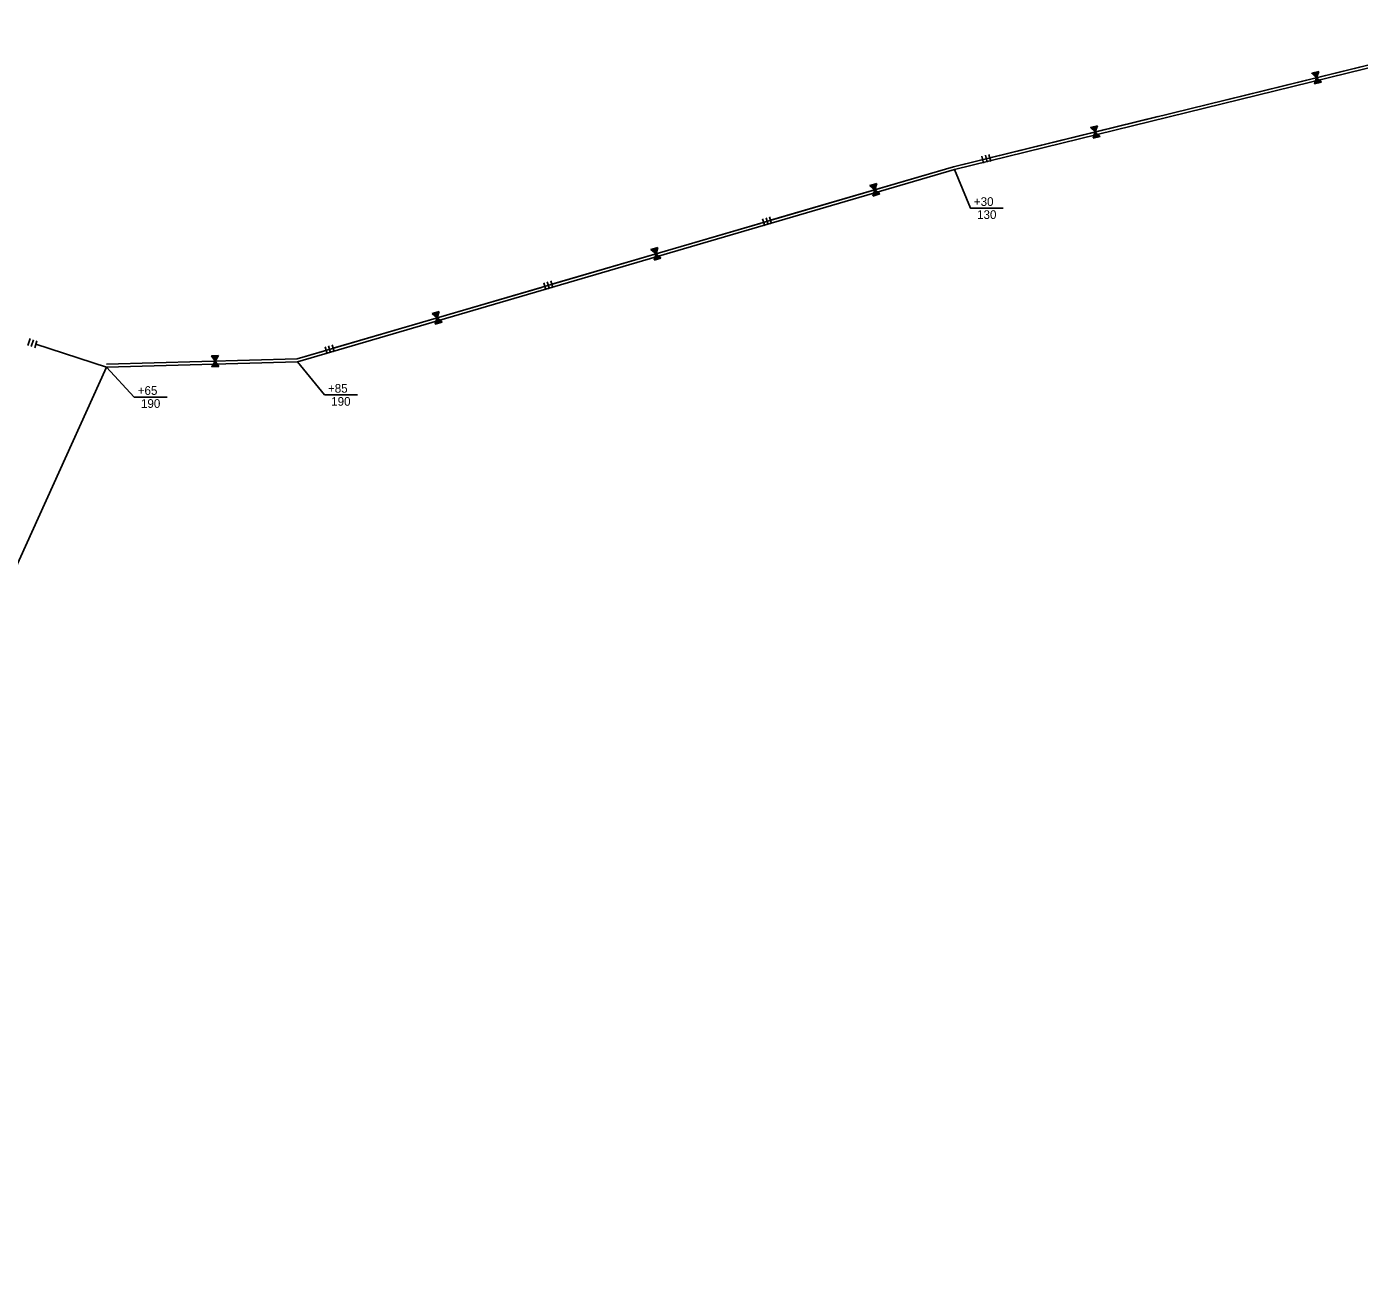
# Model space of a CAD drawing. Extents: x 979729 to 993523, y 1834148 to 1845433.
# Drawn here: x 984124 to 985045, y 1836905 to 1837770 of the extents above; entities that cross this region are included whole.
import ezdxf

# ---------------------------------------------------------------- set-up
doc = ezdxf.new("R2010")
doc.units = 0
for name, color, linetype in [('42', 7, 'Continuous'), ('51', 7, 'Continuous'), ('R_Draft', 7, 'Continuous')]:
    doc.layers.add(name, color=color, linetype=linetype)

msp = doc.modelspace()

# ---------------------------------------------------------------- linework, layer by layer
at = {"layer": '42'}
for p, q in [((984764.91, 1837673.05), (985159.48, 1837769.83)), ((985012.42, 1837737.62), (985015.74, 1837734.58)), ((985012.49, 1837737.58), (985012.51, 1837737.64)), ((985012.69, 1837737.42), (985012.8, 1837737.72)), ((985012.89, 1837737.22), (985013.09, 1837737.79)), ((985013.09, 1837737.05), (985013.38, 1837737.86)), ((985013.28, 1837736.85), (985013.68, 1837737.93)), ((985013.48, 1837736.65), (985013.97, 1837738)), ((985013.68, 1837736.49), (985014.26, 1837738.07)), ((985013.91, 1837736.38), (985014.49, 1837737.99)), ((985014.09, 1837736.15), (985014.84, 1837738.22)), ((985014.2, 1837730.34), (985015.74, 1837734.58)), ((985014.3, 1837735.98), (985015.14, 1837738.29)), ((985014.48, 1837735.75), (985015.43, 1837738.36)), ((985014.7, 1837735.62), (985015.72, 1837738.43)), ((985014.88, 1837735.39), (985016.01, 1837738.5)), ((985015.01, 1837732.42), (985016.63, 1837730.93)), ((985015.09, 1837735.23), (985016.3, 1837738.58)), ((985015.11, 1837732.66), (985016.92, 1837731)), ((985015.17, 1837732.95), (985017.21, 1837731.08)), ((985015.28, 1837735.02), (985016.59, 1837738.65)), ((985015.3, 1837733.17), (985017.51, 1837731.15)), ((985015.36, 1837733.46), (985017.8, 1837731.22)), ((985015.46, 1837733.7), (985018.09, 1837731.29)), ((985015.5, 1837734.89), (985016.89, 1837738.72)), ((985015.54, 1837733.97), (985018.38, 1837731.36)), ((985015.67, 1837734.19), (985018.67, 1837731.43)), ((985015.68, 1837734.66), (985017.18, 1837738.79)), ((985015.72, 1837734.48), (985018.96, 1837731.51)), ((985015.74, 1837734.58), (985017.27, 1837738.81)), ((985015.74, 1837734.58), (985019.06, 1837731.53)), ((985014.25, 1837730.41), (985014.29, 1837730.36)), ((985014.35, 1837730.65), (985014.59, 1837730.43)), ((985014.43, 1837730.91), (985014.88, 1837730.5)), ((985014.54, 1837731.15), (985015.17, 1837730.58)), ((985014.62, 1837731.42), (985015.46, 1837730.65)), ((985014.69, 1837731.69), (985015.75, 1837730.72)), ((985014.8, 1837731.93), (985016.05, 1837730.79)), ((985014.96, 1837732.13), (985016.21, 1837730.97)), ((984859.45, 1837700.1), (984862.77, 1837697.06)), ((984859.52, 1837700.07), (984859.54, 1837700.13)), ((984859.73, 1837699.9), (984859.83, 1837700.2)), ((984859.92, 1837699.7), (984860.13, 1837700.27)), ((984860.13, 1837699.54), (984860.42, 1837700.34)), ((984860.32, 1837699.33), (984860.71, 1837700.41)), ((984860.51, 1837699.13), (984861, 1837700.48)), ((984860.72, 1837698.97), (984861.29, 1837700.56)), ((984860.95, 1837698.87), (984861.53, 1837700.47)), ((984861.13, 1837698.63), (984861.88, 1837700.7)), ((984861.24, 1837692.82), (984862.77, 1837697.06)), ((984861.33, 1837698.46), (984862.17, 1837700.77)), ((984861.52, 1837698.24), (984862.46, 1837700.84)), ((984861.73, 1837698.1), (984862.75, 1837700.91)), ((984861.92, 1837697.87), (984863.04, 1837700.99)), ((984862.12, 1837697.71), (984863.34, 1837701.06)), ((984862.31, 1837697.5), (984863.63, 1837701.13)), ((984862.33, 1837695.65), (984864.54, 1837693.63)), ((984862.39, 1837695.94), (984864.83, 1837693.7)), ((984862.5, 1837696.18), (984865.12, 1837693.77)), ((984862.53, 1837697.37), (984863.92, 1837701.2)), ((984862.57, 1837696.45), (984865.41, 1837693.84)), ((984862.7, 1837696.67), (984865.71, 1837693.92)), ((984862.71, 1837697.14), (984864.21, 1837701.27)), ((984862.76, 1837696.96), (984866, 1837693.99)), ((984862.77, 1837697.06), (984864.31, 1837701.3)), ((984862.77, 1837697.06), (984866.09, 1837694.01)), ((984861.28, 1837692.89), (984861.33, 1837692.84)), ((984861.39, 1837693.13), (984861.62, 1837692.91)), ((984861.46, 1837693.4), (984861.91, 1837692.99)), ((984861.57, 1837693.64), (984862.2, 1837693.06)), ((984861.65, 1837693.91), (984862.5, 1837693.13)), ((984861.73, 1837694.17), (984862.79, 1837693.2)), ((984861.83, 1837694.41), (984863.08, 1837693.27)), ((984861.99, 1837694.61), (984863.25, 1837693.46)), ((984862.04, 1837694.9), (984863.66, 1837693.42)), ((984862.15, 1837695.15), (984863.96, 1837693.49)), ((984862.2, 1837695.43), (984864.25, 1837693.56)), ((984784.48, 1837680.43), (984785.67, 1837675.57)), ((984786.91, 1837681.03), (984788.1, 1837676.17)), ((984789.34, 1837681.62), (984790.53, 1837676.76)), ((984311.29, 1837540.32), (984764.91, 1837673.05)), ((984707, 1837660.02), (984710.46, 1837657.12)), ((984707.07, 1837659.98), (984707.09, 1837660.05)), ((984707.29, 1837659.83), (984707.38, 1837660.13)), ((984707.49, 1837659.63), (984707.67, 1837660.21)), ((984707.7, 1837659.48), (984707.96, 1837660.3)), ((984707.9, 1837659.29), (984708.25, 1837660.38)), ((984708.11, 1837659.1), (984708.54, 1837660.47)), ((984708.32, 1837658.94), (984708.82, 1837660.55)), ((984708.55, 1837658.85), (984709.06, 1837660.48)), ((984708.74, 1837658.62), (984709.4, 1837660.72)), ((984708.96, 1837658.46), (984709.69, 1837660.8)), ((984709.15, 1837658.24), (984709.98, 1837660.89)), ((984709.37, 1837658.12), (984710.27, 1837660.97)), ((984709.56, 1837657.9), (984710.55, 1837661.06)), ((984709.78, 1837657.74), (984710.84, 1837661.14)), ((984709.98, 1837657.55), (984711.13, 1837661.23)), ((984710.2, 1837657.42), (984711.42, 1837661.31)), ((984710.39, 1837657.2), (984711.71, 1837661.4)), ((984710.46, 1837657.12), (984711.8, 1837661.42)), ((984709.11, 1837652.82), (984710.46, 1837657.12)), ((984709.15, 1837652.89), (984709.2, 1837652.85)), ((984709.25, 1837653.13), (984709.49, 1837652.93)), ((984709.31, 1837653.41), (984709.78, 1837653.02)), ((984709.41, 1837653.65), (984710.07, 1837653.1)), ((984709.47, 1837653.92), (984710.35, 1837653.18)), ((984709.54, 1837654.19), (984710.64, 1837653.27)), ((984709.64, 1837654.44), (984710.93, 1837653.35)), ((984709.78, 1837654.64), (984711.09, 1837653.55)), ((984709.82, 1837654.94), (984711.51, 1837653.52)), ((984709.92, 1837655.18), (984711.8, 1837653.61)), ((984709.96, 1837655.47), (984712.08, 1837653.69)), ((984710.08, 1837655.7), (984712.37, 1837653.78)), ((984710.12, 1837655.99), (984712.66, 1837653.86)), ((984710.22, 1837656.23), (984712.95, 1837653.94)), ((984710.28, 1837656.51), (984713.24, 1837654.03)), ((984710.4, 1837656.73), (984713.53, 1837654.11)), ((984710.45, 1837657.02), (984713.81, 1837654.2)), ((984710.46, 1837657.12), (984713.91, 1837654.23)), ((984632.97, 1837637.05), (984634.38, 1837632.26)), ((984635.37, 1837637.76), (984636.78, 1837632.96)), ((984637.77, 1837638.46), (984639.18, 1837633.66)), ((984555.84, 1837615.79), (984559.3, 1837612.89)), ((984555.91, 1837615.75), (984555.93, 1837615.81)), ((984556.13, 1837615.6), (984556.22, 1837615.9)), ((984556.33, 1837615.4), (984556.51, 1837615.98)), ((984556.54, 1837615.25), (984556.8, 1837616.07)), ((984556.74, 1837615.06), (984557.09, 1837616.15)), ((984556.94, 1837614.86), (984557.37, 1837616.24)), ((984557.16, 1837614.71), (984557.66, 1837616.32)), ((984557.39, 1837614.61), (984557.9, 1837616.25)), ((984557.58, 1837614.39), (984558.24, 1837616.49)), ((984557.8, 1837614.23), (984558.53, 1837616.57)), ((984557.95, 1837608.59), (984559.3, 1837612.89)), ((984557.99, 1837614.01), (984558.82, 1837616.66)), ((984558.21, 1837613.88), (984559.11, 1837616.74)), ((984558.4, 1837613.66), (984559.39, 1837616.83)), ((984558.62, 1837613.51), (984559.68, 1837616.91)), ((984558.82, 1837613.32), (984559.97, 1837616.99)), ((984559.04, 1837613.19), (984560.26, 1837617.08)), ((984559.23, 1837612.97), (984560.55, 1837617.16)), ((984559.28, 1837612.79), (984562.65, 1837609.97)), ((984559.3, 1837612.89), (984560.64, 1837617.19)), ((984559.3, 1837612.89), (984562.75, 1837609.99)), ((984557.99, 1837608.66), (984558.04, 1837608.62)), ((984558.09, 1837608.9), (984558.33, 1837608.7)), ((984558.15, 1837609.17), (984558.62, 1837608.78)), ((984558.25, 1837609.42), (984558.9, 1837608.87)), ((984558.31, 1837609.69), (984559.19, 1837608.95)), ((984558.38, 1837609.96), (984559.48, 1837609.04)), ((984558.47, 1837610.21), (984559.77, 1837609.12)), ((984558.62, 1837610.41), (984559.93, 1837609.31)), ((984558.66, 1837610.71), (984560.35, 1837609.29)), ((984558.76, 1837610.95), (984560.63, 1837609.37)), ((984558.8, 1837611.24), (984560.92, 1837609.46)), ((984558.92, 1837611.47), (984561.21, 1837609.54)), ((984558.96, 1837611.76), (984561.5, 1837609.63)), ((984559.06, 1837612), (984561.79, 1837609.71)), ((984559.12, 1837612.27), (984562.08, 1837609.8)), ((984559.24, 1837612.5), (984562.36, 1837609.88)), ((984486.61, 1837594.23), (984488.02, 1837589.43)), ((984481.81, 1837592.82), (984483.22, 1837588.02)), ((984484.21, 1837593.52), (984485.62, 1837588.73)), ((984404.68, 1837571.56), (984408.13, 1837568.66)), ((984404.75, 1837571.52), (984404.77, 1837571.58)), ((984404.97, 1837571.37), (984405.06, 1837571.67)), ((984405.17, 1837571.17), (984405.35, 1837571.75)), ((984405.38, 1837571.02), (984405.64, 1837571.84)), ((984405.58, 1837570.82), (984405.92, 1837571.92)), ((984405.78, 1837570.63), (984406.21, 1837572)), ((984406, 1837570.48), (984406.5, 1837572.09)), ((984406.23, 1837570.38), (984406.74, 1837572.01)), ((984406.42, 1837570.15), (984407.08, 1837572.26)), ((984406.63, 1837570), (984407.37, 1837572.34)), ((984406.79, 1837564.36), (984408.13, 1837568.66)), ((984406.83, 1837569.78), (984407.65, 1837572.43)), ((984407.05, 1837569.65), (984407.94, 1837572.51)), ((984407.24, 1837569.43), (984408.23, 1837572.59)), ((984407.45, 1837569.28), (984408.52, 1837572.68)), ((984407.59, 1837566.72), (984409.47, 1837565.14)), ((984407.64, 1837567.01), (984409.76, 1837565.23)), ((984407.66, 1837569.08), (984408.81, 1837572.76)), ((984407.76, 1837567.24), (984410.05, 1837565.31)), ((984407.8, 1837567.53), (984410.34, 1837565.4)), ((984407.88, 1837568.96), (984409.1, 1837572.85)), ((984407.9, 1837567.77), (984410.63, 1837565.48)), ((984407.96, 1837568.04), (984410.91, 1837565.56)), ((984408.07, 1837568.74), (984409.38, 1837572.93)), ((984408.08, 1837568.27), (984411.2, 1837565.65)), ((984408.12, 1837568.56), (984411.49, 1837565.73)), ((984408.13, 1837568.66), (984409.48, 1837572.96)), ((984408.13, 1837568.66), (984411.59, 1837565.76)), ((984406.83, 1837564.43), (984406.88, 1837564.38)), ((984406.92, 1837564.67), (984407.17, 1837564.47)), ((984406.99, 1837564.94), (984407.45, 1837564.55)), ((984407.09, 1837565.19), (984407.74, 1837564.64)), ((984407.15, 1837565.46), (984408.03, 1837564.72)), ((984407.22, 1837565.73), (984408.32, 1837564.81)), ((984407.31, 1837565.98), (984408.61, 1837564.89)), ((984407.46, 1837566.18), (984408.77, 1837565.08)), ((984407.5, 1837566.47), (984409.18, 1837565.06)), ((984126.82, 1837554.28), (984125.28, 1837549.53)), ((984129.2, 1837553.52), (984127.66, 1837548.76)), ((984131.57, 1837552.75), (984130.04, 1837547.99)), ((984330.65, 1837548.59), (984332.06, 1837543.79)), ((984333.05, 1837549.29), (984334.45, 1837544.49)), ((984335.45, 1837550), (984336.85, 1837545.2)), ((984179.75, 1837536.6), (984311.29, 1837540.32)), ((984252.11, 1837542.4), (984254.72, 1837538.72)), ((984252.17, 1837542.35), (984252.21, 1837542.4)), ((984252.34, 1837542.14), (984252.51, 1837542.41)), ((984252.48, 1837541.9), (984252.81, 1837542.42)), ((984252.65, 1837541.7), (984253.11, 1837542.43)), ((984252.8, 1837541.46), (984253.41, 1837542.44)), ((984252.94, 1837541.23), (984253.71, 1837542.44)), ((984253.11, 1837541.02), (984254.01, 1837542.45)), ((984253.31, 1837540.87), (984254.22, 1837542.32)), ((984253.44, 1837540.6), (984254.61, 1837542.47)), ((984253.61, 1837540.4), (984254.91, 1837542.48)), ((984253.74, 1837540.14), (984255.21, 1837542.49)), ((984253.92, 1837539.96), (984255.51, 1837542.5)), ((984254.05, 1837539.7), (984255.81, 1837542.5)), ((984254.22, 1837539.49), (984256.11, 1837542.51)), ((984254.36, 1837539.25), (984256.41, 1837542.52)), ((984254.55, 1837539.07), (984256.71, 1837542.53)), ((984254.68, 1837538.81), (984257.01, 1837542.54)), ((984254.72, 1837538.72), (984257.11, 1837542.54)), ((984252.32, 1837534.9), (984254.72, 1837538.72)), ((984252.38, 1837534.96), (984252.42, 1837534.9)), ((984252.54, 1837535.17), (984252.72, 1837534.91)), ((984252.67, 1837535.42), (984253.02, 1837534.92)), ((984252.82, 1837535.63), (984253.32, 1837534.93)), ((984252.96, 1837535.88), (984253.62, 1837534.94)), ((984253.09, 1837536.12), (984253.92, 1837534.95)), ((984253.24, 1837536.33), (984254.22, 1837534.96)), ((984253.44, 1837536.49), (984254.42, 1837535.1)), ((984253.55, 1837536.77), (984254.82, 1837534.97)), ((984253.7, 1837536.98), (984255.12, 1837534.98)), ((984253.82, 1837537.25), (984255.42, 1837534.99)), ((984253.99, 1837537.44), (984255.72, 1837535)), ((984254.11, 1837537.71), (984256.02, 1837535.01)), ((984254.26, 1837537.92), (984256.32, 1837535.02)), ((984254.39, 1837538.17), (984256.62, 1837535.02)), ((984254.57, 1837538.36), (984256.92, 1837535.03)), ((984254.68, 1837538.63), (984257.22, 1837535.04)), ((984254.72, 1837538.72), (984257.32, 1837535.04))]:
    msp.add_line(p, q, dxfattribs=at)
for points in [[(984954.54, 1837719.57), (985088.58, 1837752.44)], [(985012.42, 1837737.62), (985017.27, 1837738.81)], [(985014.2, 1837730.34), (985019.06, 1837731.53)], [(984789.93, 1837679.19), (984905.94, 1837707.65)], [(984859.45, 1837700.1), (984864.31, 1837701.3)], [(984861.24, 1837692.82), (984866.09, 1837694.01)], [(984638.48, 1837636.06), (984764.91, 1837673.05), (984782.65, 1837677.41)], [(984707, 1837660.02), (984711.8, 1837661.42)], [(984709.11, 1837652.82), (984713.91, 1837654.23)], [(984487.31, 1837591.83), (984631.28, 1837633.95)], [(984555.84, 1837615.79), (984560.64, 1837617.19)], [(984557.95, 1837608.59), (984562.75, 1837609.99)], [(984336.15, 1837547.6), (984480.12, 1837589.72)], [(984404.68, 1837571.56), (984409.48, 1837572.96)], [(984406.79, 1837564.36), (984411.59, 1837565.76)], [(984130.81, 1837550.37), (984179.74, 1837534.6)], [(984179.75, 1837536.6), (984311.29, 1837540.32), (984328.95, 1837545.49)], [(984252.11, 1837542.4), (984257.11, 1837542.54)], [(984252.32, 1837534.9), (984257.32, 1837535.04)]]:
    msp.add_lwpolyline(points, dxfattribs=at)
at = {"layer": '51'}
msp.add_lwpolyline([(983832.14, 1837610.35), (983899.28, 1837624.99), (983877.1, 1837385.75), (983914.53, 1837124.26), (983905.65, 1836909.01), (984013.18, 1836905.08), (984017.58, 1837080.16), (984054.32, 1837258.25), (984179.74, 1837534.6), (984311.6, 1837538.33), (984765.43, 1837671.12), (985159.91, 1837767.88)], dxfattribs=at)
at = {"layer": 'R_Draft'}
for p, q in [((984782.51, 1837644.47), (984799.27, 1837644.47)), ((984204.84, 1837513.96), (984221.6, 1837513.96)), ((984336.27, 1837515.43), (984353.03, 1837515.43))]:
    msp.add_line(p, q, dxfattribs=at)
for points in [[(984765.43, 1837671.12), (984776.51, 1837644.47), (984782.51, 1837644.47)], [(984179.74, 1837534.6), (984198.84, 1837513.96), (984204.84, 1837513.96)], [(984311.6, 1837538.33), (984330.27, 1837515.43), (984336.27, 1837515.43)]]:
    msp.add_lwpolyline(points, dxfattribs=at)

# ---------------------------------------------------------------- texts
for s, p in [('+30', (984778.89, 1837645.97)), (' 130', (984778.89, 1837636.97)), ('+65', (984201.21, 1837515.46)), ('+85', (984332.64, 1837516.93)), (' 190', (984201.21, 1837506.46)), (' 190', (984332.64, 1837507.93))]:
    msp.add_text(s, height=6, rotation=360, dxfattribs=at).set_placement(p)

doc.saveas('drawing.dxf')
